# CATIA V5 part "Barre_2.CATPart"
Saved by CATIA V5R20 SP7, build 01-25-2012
Part number: Barre_2
Bounding box of the stored display mesh (mm): x 0 to 8, y 18.193 to 32.173, z -0.048 to 11.42
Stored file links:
  J:\IFMA\IAO\système avant mef\Barre_2.CATPart
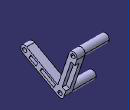
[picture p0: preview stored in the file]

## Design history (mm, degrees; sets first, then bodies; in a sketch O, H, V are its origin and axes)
Body1 (main body)
  Plane1: stored without definition
  Point1 "Point.A": stored without definition
  Plane2: stored without definition
  Point2 "Point.B": stored without definition
  Point3 "Point.A": stored without definition
  Point4 "Point.B": stored without definition
  Plane3: stored without definition
  Point5 "Point.M": stored without definition
  Point6 "Point.B": stored without definition
  Point7 "Point.A": stored without definition
  Point8 "Point.A": stored without definition
  Plane4: stored without definition
  Sketch1 on Plane3, origin (6, 0, 0), H (0, 1, 0), V (0, 0, 1)
    construction line L1 (31.1733, 10.4199) -> (27.9546, 0.9521)
    point P1 (31.1733, 10.4199)
    point P2 (27.9546, 0.9521)
    line L2 (32.1201, 10.0981) -> (28.9014, 0.6303)
    line L3 (27.0078, 1.274) -> (30.2266, 10.7418)
    arc A1 centre (27.9546, 0.9521) radius 1 from (28.9014, 0.6303) to (27.0078, 1.274) cw
    arc A2 centre (31.1733, 10.4199) radius 1 from (30.2266, 10.7418) to (32.1201, 10.0981) cw
    reference projected point E1 (27.9546, 0.9521) from Point6
    reference projected point E2 (31.1733, 10.4199) from Point7
    reference projected point E3 (31.1733, 10.4199) from Point8
    distance L2 L1 = 1
    tangency: A1 L2, A2 L2, A1 L3, A2 L3
    coincidence: P2 E1, L1 E2, P1 E3
  Pad1: profile Sketch1, direction (1, 0, 0), length 2
  Point9 "Point.M": stored without definition
  Point10 "Point.B": stored without definition
  Plane5: stored without definition
  Sketch2 on Plane4, origin (6, 0, 0), H (0, 1, 0), V (0, 0, 1)
    construction line L1 (19.1895, 5.7661) -> (27.9546, 0.9521)
    point P1 (19.1895, 5.7661)
    point P2 (27.9546, 0.9521)
    line L2 (19.6709, 6.6426) -> (28.436, 1.8286)
    line L3 (27.4732, 0.0756) -> (18.7081, 4.8896)
    arc A1 centre (27.9546, 0.9521) radius 1 from (28.436, 1.8286) to (27.4732, 0.0756) cw
    arc A2 centre (19.1895, 5.7661) radius 1 from (18.7081, 4.8896) to (19.6709, 6.6426) cw
    reference projected point E1 (19.1895, 5.7661) from Point9
    reference projected point E2 (27.9546, 0.9521) from Point10
    distance L1 L2 = 1
    tangency: A1 L2, A2 L2, A1 L3, A2 L3
    coincidence: E1 P1, P2 E2
  Pad2: profile Sketch2, direction (1, 0, 0), length 2
  Point11 "Point.B": stored without definition
  Plane6: stored without definition
  Sketch3 on Plane5, origin (6, 0, 0), H (0, 1, 0), V (0, 0, 1)
    circle A1 centre (27.9546, 0.9521) radius 1
    point P1 (27.9546, 0.9521)
    reference projected point E1 (27.9546, 0.9521) from Point11
    radius A1 = 1
    coincidence: P1 E1
  Pad3: profile Sketch3, direction (-1, 0, 0), length 6
  Plane7: stored without definition
  Point12 "Point.A": stored without definition
  Point13 "Point.A": stored without definition
  Sketch4 on Plane7, origin (6, 0, 0), H (0, 1, 0), V (0, 0, 1)
    circle A1 centre (31.1733, 10.4199) radius 1
    point P1 (31.1733, 10.4199)
    reference projected point E1 (31.1733, 10.4199) from Point13
    radius A1 = 1
    coincidence: P1 E1
  Pad4: profile Sketch4, direction (-1, 0, 0), length 6
  Sketch5 on face of Pad2, origin (8, 21.2494, 4.7256), H (0, 1, 0), V (0, 0, 1)
    point P1 (-2.0599, 1.0405)
    reference projected point E1 (-2.0599, 1.0405) from Point14
    coincidence: P1 E1
  Hole1: placed by Sketch5, at (8, 19.1895, 5.7661) direction (-1, 0, 0), diameter 1, through (limit type 3)
  Sketch6 on end face of Pad4, origin (0, 31.1733, 10.4199), H (0, 1, 0), V (0, 0, -1)
    point P1 (0, 0)
    reference projected point E1 (0, 0) from Point15
    coincidence: P1 E1
  Hole2: placed by Sketch6, at (0, 31.1733, 10.4199) direction (1, 0, 0), diameter 1, through (limit type 3)
  Sketch7 on end face of Pad3, origin (0, 27.9546, 0.9521), H (0, 1, 0), V (0, 0, -1)
    point P1 (0, 0)
    reference projected point E1 (0, 0) from Point16
    coincidence: P1 E1
  Hole3: placed by Sketch7, at (0, 27.9546, 0.9521) direction (1, 0, 0), diameter 1, through (limit type 3)
  Sketch8 on face of Pad2, origin (8, 0, 0), H (0, 1, 0), V (0, 0, 1)
    line L1 (20.7011, 5.4633) -> (22.4356, 4.5107)
    line L2 (22.4356, 4.5107) -> (21.9949, 3.7083)
    line L3 (21.9949, 3.7083) -> (20.2604, 4.661)
    line L4 (20.2604, 4.661) -> (20.7011, 5.4633)
    reference projected line E1 (18.7081, 4.8896) -> (27.4732, 0.0756) from edge [face of Pad2 from Sketch2.L3 | face of Pad2]
    line L5 (23.4393, 4.0065) -> (26.8362, 2.1408)
    line L6 (26.8362, 2.1408) -> (26.4001, 1.3468)
    line L7 (26.4001, 1.3468) -> (23.0032, 3.2124)
    line L8 (23.0032, 3.2124) -> (23.4393, 4.0065)
    reference projected line E2 (18.7081, 4.8896) -> (27.4732, 0.0756) from edge [face of Pad2 from Sketch2.L3 | face of Pad2]
    perpendicularity: L2 L1, L6 L5, L8 L5
    parallelism: L3 L1, L4 L2, L3 E1, L7 L5, E2 L7
  Pocket1: profile Sketch8, direction (-1, 0, 0), through (limit type 3)
  Sketch9 on face of Pad2, origin (8, 0, 0), H (0, 1, 0), V (0, 0, 1)
    line L1 (28.4552, 2.4248) -> (30.6612, 8.9134)
    line L2 (30.6612, 8.9134) -> (32.2568, 8.3709)
    line L3 (32.2568, 8.3709) -> (30.0509, 1.8823)
    line L4 (30.0509, 1.8823) -> (28.4552, 2.4248)
    reference projected line E1 (30.2266, 10.7418) -> (27.0078, 1.274) from edge [face of Pad1 from Sketch1.L3 | face of Pad2]
    reference projected line E2 (30.2266, 10.7418) -> (27.0078, 1.274) from edge [face of Pad1 from Sketch1.L3 | face of Pad2]
    distance L1 E2 = 1
    perpendicularity: L2 L1
    parallelism: L3 L1, L4 L2, L1 E1
  Pocket2: profile Sketch9, direction (-1, 0, 0), length 1
  Point14 "Point.M": stored without definition
  Point15 "Point.A": stored without definition
  Point16 "Point.B": stored without definition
